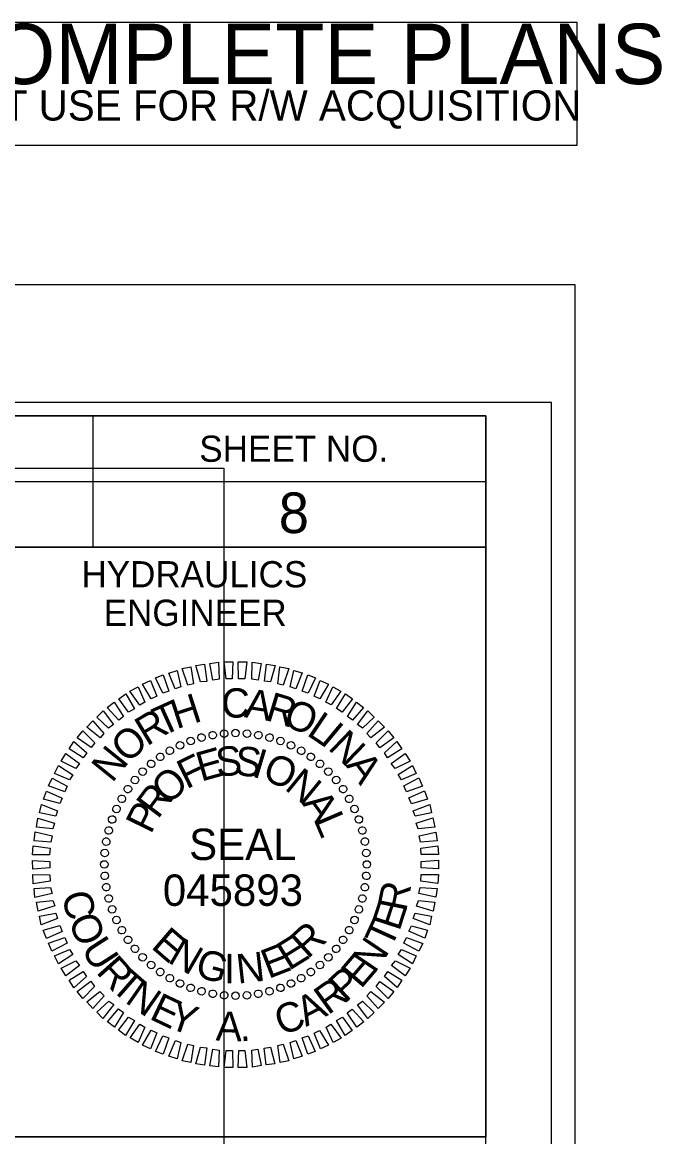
# Model space of a CAD drawing. Extents: x 1623313 to 1628771, y 891211 to 901910.
# Drawn here: x 1624891.5 to 1625013.5, y 901696.9 to 901909.5 of the extents above; entities that cross this region are included whole.
import ezdxf

# ---------------------------------------------------------------- set-up
doc = ezdxf.new("R2010")
doc.units = 0
for name, color, linetype in [('Default', 7, 'Continuous'), ('Prop Plan Preparation Cover Label', 7, 'Continuous'), ('Scratch_Level_0', 7, 'Continuous'), ('Sheet Cutting Line CELL', 7, 'Continuous'), ('Sheet Data Field CELL', 7, 'Continuous'), ('Sheet Plot Border Inside CELL', 7, 'Continuous'), ('Sheet Plot Border Outside CELL', 7, 'Continuous'), ('Sheet Profile CELL', 7, 'Continuous'), ('Sheet Sticker Exception Certification CELL', 7, 'Continuous')]:
    doc.layers.add(name, color=color, linetype=linetype)

msp = doc.modelspace()

# ---------------------------------------------------------------- linework, layer by layer
at = {"layer": 'Default'}
for p, q in [((1624929.97, 901773.77), (1624929.97, 901773.77)), ((1624932.17, 901773.92), (1624932.17, 901773.92)), ((1624934.37, 901773.77), (1624934.37, 901773.77)), ((1624921.62, 901771.52), (1624921.62, 901771.52)), ((1624923.57, 901772.37), (1624923.57, 901772.37)), ((1624925.67, 901773.02), (1624925.67, 901773.02)), ((1624927.82, 901773.47), (1624927.82, 901773.47)), ((1624936.52, 901773.47), (1624936.52, 901773.47)), ((1624938.67, 901773.02), (1624938.67, 901773.02)), ((1624940.77, 901772.37), (1624940.77, 901772.37)), ((1624942.77, 901771.52), (1624942.77, 901771.52)), ((1624917.82, 901769.32), (1624917.82, 901769.32)), ((1624919.67, 901770.52), (1624919.67, 901770.52)), ((1624944.72, 901770.52), (1624944.72, 901770.52)), ((1624946.52, 901769.37), (1624946.52, 901769.37)), ((1624916.02, 901768.07), (1624916.02, 901768.07)), ((1624948.32, 901768.02), (1624948.32, 901768.02)), ((1624914.42, 901766.52), (1624914.42, 901766.52)), ((1624949.87, 901766.57), (1624949.87, 901766.57)), ((1624911.62, 901763.17), (1624911.62, 901763.17)), ((1624912.92, 901764.97), (1624912.92, 901764.97)), ((1624951.42, 901764.92), (1624951.42, 901764.92)), ((1624952.67, 901763.17), (1624952.67, 901763.17)), ((1624910.42, 901761.32), (1624910.42, 901761.32)), ((1624953.87, 901761.32), (1624953.87, 901761.32)), ((1624909.42, 901759.37), (1624909.42, 901759.37)), ((1624954.87, 901759.37), (1624954.87, 901759.37)), ((1624908.57, 901757.37), (1624908.57, 901757.37)), ((1624955.72, 901757.37), (1624955.72, 901757.37)), ((1624907.92, 901755.32), (1624907.92, 901755.32)), ((1624956.37, 901755.32), (1624956.37, 901755.32)), ((1624907.47, 901753.17), (1624907.47, 901753.17)), ((1624956.82, 901753.12), (1624956.82, 901753.12)), ((1624907.17, 901751.02), (1624907.17, 901751.02)), ((1624957.12, 901750.97), (1624957.12, 901750.97)), ((1624907.07, 901748.82), (1624907.07, 901748.82)), ((1624957.27, 901748.77), (1624957.27, 901748.77)), ((1624907.22, 901746.62), (1624907.22, 901746.62)), ((1624957.17, 901746.57), (1624957.17, 901746.57)), ((1624907.52, 901744.47), (1624907.52, 901744.47)), ((1624956.87, 901744.47), (1624956.87, 901744.47)), ((1624907.97, 901742.32), (1624907.97, 901742.32)), ((1624956.37, 901742.27), (1624956.37, 901742.27)), ((1624908.62, 901740.22), (1624908.62, 901740.22)), ((1624955.72, 901740.22), (1624955.72, 901740.22)), ((1624909.47, 901738.22), (1624909.47, 901738.22)), ((1624954.92, 901738.22), (1624954.92, 901738.22)), ((1624910.47, 901736.27), (1624910.47, 901736.27)), ((1624953.92, 901736.27), (1624953.92, 901736.27)), ((1624911.67, 901734.42), (1624911.67, 901734.42)), ((1624952.72, 901734.42), (1624952.72, 901734.42)), ((1624912.92, 901732.67), (1624912.92, 901732.67)), ((1624914.42, 901731.07), (1624914.42, 901731.07)), ((1624949.92, 901731.07), (1624949.92, 901731.07)), ((1624951.37, 901732.67), (1624951.37, 901732.67)), ((1624916.02, 901729.57), (1624916.02, 901729.57)), ((1624948.27, 901729.57), (1624948.27, 901729.57)), ((1624917.77, 901728.27), (1624917.77, 901728.27)), ((1624919.62, 901727.07), (1624919.62, 901727.07)), ((1624944.72, 901727.07), (1624944.72, 901727.07)), ((1624946.52, 901728.32), (1624946.52, 901728.32)), ((1624921.57, 901726.07), (1624921.57, 901726.07)), ((1624923.57, 901725.22), (1624923.57, 901725.22)), ((1624940.72, 901725.22), (1624940.72, 901725.22)), ((1624942.72, 901726.07), (1624942.72, 901726.07)), ((1624925.67, 901724.57), (1624925.67, 901724.57)), ((1624927.82, 901724.12), (1624927.82, 901724.12)), ((1624929.97, 901723.82), (1624929.97, 901723.82)), ((1624932.12, 901723.72), (1624932.12, 901723.72)), ((1624934.32, 901723.87), (1624934.32, 901723.87)), ((1624936.52, 901724.12), (1624936.52, 901724.12)), ((1624938.67, 901724.57), (1624938.67, 901724.57))]:
    msp.add_line(p, q, dxfattribs=at)
for points in [[(1624923.07, 901783.07), (1624921.97, 901786.22), (1624923.67, 901786.57), (1624924.12, 901783.32)], [(1624925.47, 901783.67), (1624924.62, 901786.82), (1624926.27, 901787.02), (1624926.67, 901783.77)], [(1624927.87, 901784.02), (1624927.27, 901787.17), (1624928.92, 901787.42), (1624929.07, 901784.17)], [(1624930.37, 901784.27), (1624930.02, 901787.52), (1624931.67, 901787.47), (1624931.52, 901784.27)], [(1624932.72, 901784.27), (1624932.67, 901787.47), (1624934.32, 901787.52), (1624933.92, 901784.27)], [(1624935.27, 901784.17), (1624935.37, 901787.42), (1624937.07, 901787.17), (1624936.47, 901784.02)], [(1624937.67, 901783.82), (1624938.07, 901787.02), (1624939.72, 901786.82), (1624938.87, 901783.67)], [(1624940.22, 901783.32), (1624940.62, 901786.57), (1624942.37, 901786.22), (1624941.27, 901783.07)], [(1624918.27, 901781.52), (1624916.92, 901784.42), (1624918.37, 901785.02), (1624919.47, 901781.87)], [(1624920.67, 901782.37), (1624919.47, 901785.32), (1624921.02, 901785.82), (1624921.72, 901782.72)], [(1624942.62, 901782.72), (1624943.27, 901785.82), (1624944.87, 901785.37), (1624943.67, 901782.37)], [(1624944.87, 901781.87), (1624945.97, 901785.02), (1624947.42, 901784.42), (1624946.02, 901781.52)], [(1624913.92, 901779.22), (1624912.02, 901781.87), (1624913.62, 901782.72), (1624914.87, 901779.82)], [(1624916.07, 901780.42), (1624914.42, 901783.22), (1624915.97, 901783.92), (1624917.17, 901780.92)], [(1624947.17, 901780.92), (1624948.32, 901783.92), (1624949.92, 901783.22), (1624948.27, 901780.42)], [(1624949.42, 901779.82), (1624950.72, 901782.72), (1624952.27, 901781.87), (1624950.42, 901779.27)], [(1624911.77, 901777.92), (1624909.92, 901780.42), (1624911.22, 901781.42), (1624912.92, 901778.52)], [(1624951.42, 901778.57), (1624953.17, 901781.42), (1624954.47, 901780.42), (1624952.52, 901777.92)], [(1624907.92, 901774.82), (1624905.72, 901776.97), (1624906.92, 901778.17), (1624908.87, 901775.52)], [(1624909.92, 901776.37), (1624907.67, 901778.77), (1624909.02, 901779.82), (1624910.82, 901777.07)], [(1624953.52, 901777.07), (1624955.27, 901779.82), (1624956.62, 901778.77), (1624954.47, 901776.37)], [(1624955.42, 901775.52), (1624957.42, 901778.17), (1624958.62, 901776.97), (1624956.37, 901774.82)], [(1624906.32, 901773.02), (1624903.77, 901775.02), (1624904.97, 901776.22), (1624907.07, 901773.82)], [(1624957.22, 901773.82), (1624959.37, 901776.22), (1624960.57, 901775.02), (1624958.02, 901773.02)], [(1624904.62, 901771.12), (1624901.97, 901773.02), (1624903.02, 901774.32), (1624905.32, 901772.02)], [(1624959.02, 901772.02), (1624961.32, 901774.32), (1624962.37, 901773.02), (1624959.72, 901771.07)], [(1624903.12, 901769.17), (1624900.42, 901770.87), (1624901.32, 901772.27), (1624903.77, 901770.12)], [(1624960.57, 901770.12), (1624962.97, 901772.32), (1624963.92, 901770.87), (1624961.17, 901769.17)], [(1624901.67, 901767.17), (1624898.87, 901768.57), (1624899.82, 901770.02), (1624902.42, 901768.07)], [(1624961.87, 901768.07), (1624964.52, 901770.02), (1624965.52, 901768.57), (1624962.62, 901767.12)], [(1624900.47, 901764.97), (1624897.62, 901766.22), (1624898.37, 901767.72), (1624901.12, 901765.92)], [(1624963.22, 901765.97), (1624965.97, 901767.72), (1624966.67, 901766.17), (1624963.82, 901764.97)], [(1624899.57, 901762.72), (1624896.47, 901763.82), (1624897.17, 901765.32), (1624900.07, 901763.77)], [(1624964.27, 901763.82), (1624967.17, 901765.37), (1624967.87, 901763.77), (1624964.77, 901762.67)], [(1624965.22, 901761.52), (1624968.22, 901762.87), (1624968.82, 901761.27), (1624965.72, 901760.42)], [(1624898.62, 901760.47), (1624895.52, 901761.32), (1624896.07, 901762.82), (1624899.12, 901761.47)], [(1624897.87, 901758.07), (1624894.77, 901758.67), (1624895.12, 901760.27), (1624898.22, 901759.07)], [(1624966.07, 901759.07), (1624969.22, 901760.27), (1624969.57, 901758.67), (1624966.42, 901758.07)], [(1624897.32, 901755.62), (1624894.17, 901755.97), (1624894.47, 901757.67), (1624897.62, 901756.72)], [(1624966.67, 901756.72), (1624969.82, 901757.72), (1624970.17, 901755.97), (1624967.02, 901755.62)], [(1624896.92, 901753.12), (1624893.72, 901753.37), (1624893.92, 901755.07), (1624897.17, 901754.32)], [(1624967.22, 901754.27), (1624970.42, 901755.02), (1624970.62, 901753.37), (1624967.47, 901753.12)], [(1624896.67, 901750.67), (1624893.42, 901750.67), (1624893.57, 901752.37), (1624896.77, 901751.92)], [(1624967.52, 901751.92), (1624970.77, 901752.42), (1624970.87, 901750.72), (1624967.62, 901750.72)], [(1624896.72, 901748.17), (1624893.47, 901747.92), (1624893.42, 901749.62), (1624896.72, 901749.37)], [(1624967.62, 901749.42), (1624970.87, 901749.67), (1624970.87, 901747.97), (1624967.62, 901748.22)], [(1624896.77, 901745.67), (1624893.57, 901745.17), (1624893.47, 901746.92), (1624896.72, 901746.87)], [(1624967.62, 901746.92), (1624970.87, 901746.92), (1624970.77, 901745.22), (1624967.52, 901745.67)], [(1624897.17, 901743.32), (1624893.87, 901742.52), (1624893.72, 901744.22), (1624896.87, 901744.47)], [(1624967.42, 901744.47), (1624970.62, 901744.22), (1624970.42, 901742.57), (1624967.17, 901743.32)], [(1624897.67, 901740.92), (1624894.52, 901739.92), (1624894.17, 901741.62), (1624897.32, 901741.97)], [(1624967.07, 901741.97), (1624970.17, 901741.62), (1624969.87, 901739.92), (1624966.72, 901740.87)], [(1624898.22, 901738.52), (1624895.07, 901737.32), (1624894.77, 901738.97), (1624897.87, 901739.57)], [(1624966.42, 901739.57), (1624969.57, 901738.97), (1624969.22, 901737.32), (1624966.07, 901738.52)], [(1624899.12, 901736.07), (1624896.12, 901734.72), (1624895.47, 901736.32), (1624898.62, 901737.17)], [(1624965.72, 901737.12), (1624968.82, 901736.27), (1624968.27, 901734.77), (1624965.22, 901736.12)], [(1624900.07, 901733.82), (1624897.12, 901732.27), (1624896.47, 901733.82), (1624899.57, 901734.92)], [(1624964.77, 901734.87), (1624967.92, 901733.77), (1624967.17, 901732.27), (1624964.27, 901733.82)], [(1624901.12, 901731.67), (1624898.37, 901729.87), (1624897.62, 901731.42), (1624900.47, 901732.62)], [(1624963.87, 901732.62), (1624966.67, 901731.42), (1624965.97, 901729.87), (1624963.22, 901731.67)], [(1624902.42, 901729.57), (1624899.82, 901727.57), (1624898.87, 901729.02), (1624901.67, 901730.47)], [(1624962.67, 901730.47), (1624965.47, 901729.02), (1624964.52, 901727.57), (1624961.92, 901729.57)], [(1624903.72, 901727.47), (1624901.32, 901725.32), (1624900.42, 901726.77), (1624903.12, 901728.42)], [(1624961.22, 901728.42), (1624963.92, 901726.77), (1624963.02, 901725.37), (1624960.57, 901727.47)], [(1624905.27, 901725.57), (1624903.02, 901723.27), (1624901.97, 901724.57), (1624904.57, 901726.57)], [(1624959.72, 901726.52), (1624962.37, 901724.57), (1624961.32, 901723.27), (1624959.02, 901725.57)], [(1624907.12, 901723.77), (1624904.92, 901721.37), (1624903.77, 901722.62), (1624906.27, 901724.57)], [(1624908.92, 901722.12), (1624906.87, 901719.47), (1624905.72, 901720.67), (1624907.97, 901722.77)], [(1624956.37, 901722.77), (1624958.62, 901720.62), (1624957.42, 901719.42), (1624955.47, 901722.07)], [(1624958.02, 901724.57), (1624960.57, 901722.57), (1624959.37, 901721.37), (1624957.22, 901723.77)], [(1624910.82, 901720.57), (1624909.07, 901717.82), (1624907.72, 901718.82), (1624909.87, 901721.27)], [(1624954.42, 901721.22), (1624956.67, 901718.82), (1624955.32, 901717.77), (1624953.47, 901720.52)], [(1624912.92, 901719.07), (1624911.17, 901716.22), (1624909.87, 901717.22), (1624911.77, 901719.67)], [(1624914.87, 901717.77), (1624913.62, 901714.87), (1624912.07, 901715.77), (1624913.92, 901718.37)], [(1624950.37, 901718.37), (1624952.32, 901715.72), (1624950.77, 901714.87), (1624949.47, 901717.77)], [(1624952.57, 901719.67), (1624954.42, 901717.17), (1624953.12, 901716.22), (1624951.42, 901719.07)], [(1624917.17, 901716.72), (1624915.97, 901713.67), (1624914.42, 901714.37), (1624916.07, 901717.22)], [(1624919.47, 901715.77), (1624918.37, 901712.62), (1624916.92, 901713.17), (1624918.32, 901716.12)], [(1624946.02, 901716.12), (1624947.37, 901713.17), (1624945.97, 901712.62), (1624944.87, 901715.77)], [(1624948.22, 901717.17), (1624949.92, 901714.37), (1624948.37, 901713.67), (1624947.17, 901716.67)], [(1624921.72, 901714.87), (1624921.02, 901711.77), (1624919.47, 901712.27), (1624920.72, 901715.22)], [(1624924.12, 901714.27), (1624923.67, 901711.07), (1624921.97, 901711.37), (1624923.07, 901714.52)], [(1624926.67, 901713.82), (1624926.27, 901710.57), (1624924.62, 901710.82), (1624925.47, 901713.97)], [(1624938.87, 901713.97), (1624939.67, 901710.77), (1624938.02, 901710.62), (1624937.62, 901713.77)], [(1624941.27, 901714.52), (1624942.37, 901711.37), (1624940.67, 901711.02), (1624940.22, 901714.27)], [(1624943.67, 901715.22), (1624944.87, 901712.27), (1624943.27, 901711.77), (1624942.57, 901714.87)], [(1624929.07, 901713.42), (1624928.92, 901710.22), (1624927.27, 901710.42), (1624927.87, 901713.57)], [(1624931.57, 901713.37), (1624931.67, 901710.12), (1624930.02, 901710.07), (1624930.37, 901713.32)], [(1624933.97, 901713.32), (1624934.32, 901710.07), (1624932.67, 901710.12), (1624932.77, 901713.37)], [(1624936.42, 901713.57), (1624937.07, 901710.47), (1624935.42, 901710.17), (1624935.27, 901713.42)]]:
    msp.add_lwpolyline(points, close=True, dxfattribs=at)
for centre, major_axis in [((1624925.69, 901773.04), (-0.186, 0.695)), ((1624927.82, 901773.52), (-0.125, 0.708)), ((1624929.99, 901773.8), (-0.063, 0.717)), ((1624932.17, 901773.9), (0, 0.719)), ((1624934.35, 901773.8), (0.063, 0.717)), ((1624936.52, 901773.52), (0.125, 0.708)), ((1624938.66, 901773.04), (0.186, 0.695)), ((1624919.64, 901770.54), (-0.36, 0.623)), ((1624921.58, 901771.55), (-0.304, 0.652)), ((1624923.6, 901772.39), (-0.246, 0.676)), ((1624940.74, 901772.39), (0.246, 0.676)), ((1624942.76, 901771.55), (0.304, 0.652)), ((1624944.7, 901770.54), (0.36, 0.623)), ((1624917.8, 901769.37), (-0.413, 0.589)), ((1624946.54, 901769.37), (0.413, 0.589)), ((1624914.45, 901766.56), (-0.509, 0.509)), ((1624916.07, 901768.03), (-0.462, 0.551)), ((1624948.28, 901768.03), (0.462, 0.551)), ((1624949.89, 901766.56), (0.509, 0.509)), ((1624912.98, 901764.95), (-0.551, 0.462)), ((1624951.36, 901764.95), (0.551, 0.462)), ((1624911.65, 901763.21), (-0.589, 0.413)), ((1624952.69, 901763.21), (0.589, 0.413)), ((1624910.47, 901761.37), (-0.623, 0.36)), ((1624953.87, 901761.37), (0.623, 0.36)), ((1624909.46, 901759.43), (-0.652, 0.304)), ((1624954.88, 901759.43), (0.652, 0.304)), ((1624908.63, 901757.41), (-0.676, 0.246)), ((1624955.71, 901757.41), (0.676, 0.246)), ((1624907.97, 901755.33), (-0.695, 0.186)), ((1624956.37, 901755.33), (0.695, 0.186)), ((1624907.5, 901753.19), (-0.708, 0.125)), ((1624956.85, 901753.19), (0.708, 0.125)), ((1624907.21, 901751.03), (-0.717, 0.063)), ((1624957.13, 901751.03), (0.717, 0.063)), ((1624907.12, 901748.84), (-0.719, 0)), ((1624957.23, 901748.84), (0.719, 0)), ((1624907.21, 901746.66), (-0.717, -0.063)), ((1624957.13, 901746.66), (0.717, -0.063)), ((1624907.5, 901744.49), (-0.708, -0.125)), ((1624956.85, 901744.49), (0.708, -0.125)), ((1624907.97, 901742.36), (-0.695, -0.186)), ((1624956.37, 901742.36), (0.695, -0.186)), ((1624908.63, 901740.27), (-0.676, -0.246)), ((1624955.71, 901740.27), (0.676, -0.246)), ((1624909.46, 901738.25), (-0.652, -0.304)), ((1624954.88, 901738.25), (0.652, -0.304)), ((1624910.47, 901736.31), (-0.623, -0.36)), ((1624911.65, 901734.47), (-0.589, -0.413)), ((1624952.69, 901734.47), (0.589, -0.413)), ((1624953.87, 901736.31), (0.623, -0.36)), ((1624912.98, 901732.74), (-0.551, -0.462)), ((1624951.36, 901732.74), (0.551, -0.462)), ((1624914.45, 901731.13), (-0.509, -0.509)), ((1624949.89, 901731.13), (0.509, -0.509)), ((1624916.07, 901729.65), (-0.462, -0.551)), ((1624917.8, 901728.32), (-0.413, -0.589)), ((1624946.54, 901728.32), (0.413, -0.589)), ((1624948.28, 901729.65), (0.462, -0.551)), ((1624919.64, 901727.14), (-0.36, -0.623)), ((1624921.58, 901726.13), (-0.304, -0.652)), ((1624942.76, 901726.13), (0.304, -0.652)), ((1624944.7, 901727.14), (0.36, -0.623)), ((1624923.6, 901725.3), (-0.246, -0.676)), ((1624925.69, 901724.64), (-0.186, -0.695)), ((1624927.82, 901724.17), (-0.125, -0.708)), ((1624929.99, 901723.88), (-0.063, -0.717)), ((1624934.35, 901723.88), (0.063, -0.717)), ((1624936.52, 901724.17), (0.125, -0.708)), ((1624938.66, 901724.64), (0.186, -0.695)), ((1624940.74, 901725.3), (0.246, -0.676)), ((1624932.17, 901723.79), (0, -0.719))]:
    msp.add_ellipse(centre, major_axis=major_axis, ratio=0.999708, dxfattribs=at)
at = {"layer": 'Prop Plan Preparation Cover Label'}
msp.add_lwpolyline([(1624850.31, 901886.02), (1624850.31, 901909.52), (1624997.31, 901909.52), (1624997.31, 901886.02)], close=True, dxfattribs=at)
at = {"layer": 'Scratch_Level_0'}
msp.add_lwpolyline([(1623529.95, 901824.45), (1624929.95, 901824.45), (1624929.95, 901334.45), (1623529.95, 901334.45)], close=True, dxfattribs=at)
at = {"layer": 'Sheet Cutting Line CELL'}
msp.add_line((1624996.95, 901859.45), (1623312.95, 901859.45), dxfattribs=at)
at = {"layer": 'Sheet Plot Border Inside CELL'}
msp.add_lwpolyline([(1623325.95, 900781.9), (1624992.45, 900781.9), (1624992.45, 901837), (1623325.95, 901837)], close=True, dxfattribs=at)
at = {"layer": 'Sheet Plot Border Outside CELL'}
msp.add_lwpolyline([(1623312.95, 900759.45), (1624996.95, 900759.45), (1624996.95, 901859.45), (1623312.95, 901859.45)], close=True, dxfattribs=at)
at = {"layer": 'Sheet Profile CELL'}
for p, q in [((1624904.95, 901834.4), (1624904.95, 901809.4)), ((1624779.9, 901821.9), (1624979.95, 901821.9))]:
    msp.add_line(p, q, dxfattribs=at)
for points in [[(1624979.95, 901834.45), (1623479.95, 901834.45), (1623479.95, 900784.45), (1624979.95, 900784.45)], [(1624779.9, 901834.45), (1624979.95, 901834.45), (1624979.95, 901809.4), (1624779.9, 901809.4)], [(1624879.95, 901809.4), (1624979.95, 901809.4), (1624979.95, 901696.9), (1624879.95, 901696.9)]]:
    msp.add_lwpolyline(points, close=True, dxfattribs=at)
at = {"layer": 'Sheet Sticker Exception Certification CELL'}
msp.add_line((1624779.9, 901696.9), (1624979.93, 901696.9), dxfattribs=at)
msp.add_line((1624779.9, 901696.9), (1624979.93, 901696.9), dxfattribs=at)

# ---------------------------------------------------------------- texts
at = {"layer": 'Default'}
for s, height, rotation, p in [('C', 5.6, 359.8514, (1624929.47, 901776.86)), ('A', 5.6, 351.2223, (1624933.71, 901776.95)), ('T', 5.6, 24.3275, (1624918.09, 901773.2)), ('H', 5.6, 17.9268, (1624920.9, 901774.62)), ('R', 5.6, 343.1874, (1624937.63, 901776.46)), ('O', 5.6, 336.242, (1624940.94, 901775.6)), ('R', 5.6, 31.2729, (1624915.24, 901771.32)), ('L', 5.6, 326.0282, (1624945.55, 901773.63)), ('I', 5.6, 320.0485, (1624948.07, 901772.1)), ('O', 5.6, 41.4867, (1624911.51, 901767.95)), ('N', 5.6, 316.0496, (1624949.65, 901770.94)), ('N', 5.6, 51.032, (1624908.62, 901764.26)), ('S', 5.6, 5.0487, (1624928.62, 901765.56)), ('S', 5.6, 354.1866, (1624931.84, 901765.93)), ('F', 5.6, 26.1465, (1624922.82, 901763.14)), ('E', 5.6, 15.6529, (1624925.59, 901764.61)), ('I', 5.6, 343.3245, (1624935.08, 901765.69)), ('O', 5.6, 336.6634, (1624937.02, 901765.24)), ('A', 5.6, 306.5043, (1624953.08, 901767.74)), ('N', 5.6, 320.7526, (1624941.34, 901763.29)), ('O', 5.6, 42.0574, (1624919.25, 901760.02)), ('R', 5.6, 53.1038, (1624917.34, 901757.33)), ('A', 5.6, 305.8367, (1624944.77, 901760.45)), ('P', 5.6, 63.7079, (1624916.02, 901754.45)), ('L', 5.6, 293.1688, (1624947.02, 901757.41)), ('SEAL', 5.992, 360, (1624923.32, 901749.68)), ('045893', 5.994, 360, (1624918.3, 901740.93)), ('C', 5.6, 284.0401, (1624898.93, 901743.08)), ('R', 5.6, 78.5969, (1624964.69, 901739.65)), ('E', 5.6, 71.9487, (1624963.42, 901735.95)), ('O', 5.6, 292.6692, (1624900.16, 901738.16)), ('R', 5.6, 42.4535, (1624945.92, 901730.69)), ('T', 5.6, 65.548, (1624961.79, 901732.55)), ('U', 5.6, 302.883, (1624902.56, 901732.65)), ('E', 5.6, 319.2324, (1624915.85, 901733.03)), ('E', 5.6, 31.8494, (1624942.36, 901728.48)), ('N', 5.6, 329.8366, (1624919.03, 901730.29)), ('E', 5.6, 21.2452, (1624938.44, 901726.96)), ('N', 5.6, 56.0027, (1624958.69, 901727.87)), ('R', 5.6, 311.7969, (1624905.42, 901728.25)), ('G', 5.6, 344.7525, (1624924.23, 901727.52)), ('I', 5.6, 359.6683, (1624929.98, 901726.19)), ('N', 5.6, 6.3293, (1624932.61, 901726.08)), ('E', 5.6, 49.3544, (1624956.09, 901724.94)), ('T', 5.6, 318.7423, (1624908.1, 901725.16)), ('P', 5.6, 42.7062, (1624953.16, 901722.34)), ('N', 5.6, 325.143, (1624910.88, 901722.62)), ('R', 5.6, 35.7608, (1624949.81, 901720)), ('E', 5.6, 334.6883, (1624915.52, 901719.45)), ('Y', 5.6, 341.3366, (1624919.03, 901717.71)), ('C', 5.6, 19.0968, (1624940.82, 901716.16)), ('A', 5.6, 27.7259, (1624945.61, 901717.82)), ('A', 5.6, 357.753, (1624928.35, 901715.26)), ('.', 5.6, 5.7878, (1624933.07, 901715.05))]:
    msp.add_text(s, height=height, rotation=rotation, dxfattribs=at).set_placement(p)
at = {"layer": 'Prop Plan Preparation Cover Label'}
for s, height, p in [('INCOMPLETE PLANS', 11.52, (1624859.26, 901897.72)), ('DO NOT USE FOR R/W ACQUISITION', 5.76, (1624862.51, 901890.77))]:
    msp.add_text(s, height=height, dxfattribs=at).set_placement(p)
at = {"layer": 'Sheet Data Field CELL'}
msp.add_text('8', height=7.75, dxfattribs=at).set_placement((1624940.42, 901812.06))
at = {"layer": 'Sheet Profile CELL'}
for s, p in [('SHEET NO.', (1624925.26, 901825.66)), ('HYDRAULICS', (1624902.76, 901801.71)), ('ENGINEER', (1624907.01, 901794.36))]:
    msp.add_text(s, height=5, dxfattribs=at).set_placement(p)

doc.saveas('drawing.dxf')
